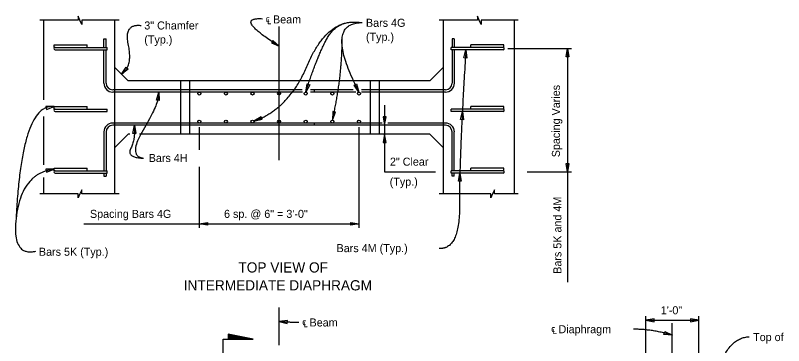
# Model space of a CAD drawing. Extents: x 120693.4 to 120747.1, y 120647.1 to 120670.1.
# Drawn here: x 120693.92 to 120708.35, y 120661.74 to 120667.95 of the extents above; entities that cross this region are included whole.
import ezdxf

# ---------------------------------------------------------------- set-up
doc = ezdxf.new("R2010")
doc.units = 0
for name, color, linetype in [('BeamConc', 7, 'Continuous'), ('CL_Major', 7, 'Continuous'), ('Dimension', 7, 'Continuous'), ('Miscellaneous', 7, 'Continuous'), ('Rebar', 7, 'Continuous'), ('TextStructures', 7, 'Continuous')]:
    doc.layers.add(name, color=color, linetype=linetype)

msp = doc.modelspace()

# ---------------------------------------------------------------- linework, layer by layer
at = {"layer": 'BeamConc'}
for p, q in [((120694.456, 120666.36), (120694.456, 120667.857)), ((120695.789, 120664.594), (120695.789, 120667.857)), ((120701.956, 120667.857), (120701.956, 120664.594)), ((120703.289, 120667.857), (120703.289, 120664.594)), ((120696.039, 120666.716), (120695.789, 120666.966)), ((120701.956, 120666.966), (120701.706, 120666.716)), ((120701.706, 120666.716), (120696.039, 120666.716)), ((120694.456, 120665.14), (120694.456, 120666.05)), ((120696.039, 120665.716), (120695.789, 120665.466)), ((120696.067, 120665.716), (120696.039, 120665.716)), ((120701.706, 120665.716), (120696.247, 120665.716)), ((120701.956, 120665.466), (120701.706, 120665.716)), ((120694.456, 120664.594), (120694.456, 120664.9))]:
    msp.add_line(p, q, dxfattribs=at)
at = {"layer": 'CL_Major'}
for p, q in [((120698.873, 120665.226), (120698.873, 120667.737)), ((120698.873, 120661.748), (120698.873, 120662.457)), ((120706.259, 120654.599), (120706.259, 120662.164))]:
    msp.add_line(p, q, dxfattribs=at)
at = {"layer": 'Dimension'}
for p, q in [((120703.171, 120667.326), (120704.365, 120667.326)), ((120704.289, 120667.326), (120704.289, 120662.934)), ((120700.855, 120666.263), (120700.855, 120665.01)), ((120697.373, 120665.848), (120697.373, 120665.419)), ((120700.373, 120665.848), (120700.373, 120663.954)), ((120697.373, 120665.1), (120697.373, 120663.954)), ((120700.855, 120665.01), (120701.812, 120665.01)), ((120703.534, 120665.009), (120704.365, 120665.009)), ((120695.206, 120664.029), (120700.373, 120664.029)), ((120705.759, 120660.46), (120705.759, 120662.293)), ((120706.759, 120660.46), (120706.759, 120662.293)), ((120705.759, 120662.218), (120706.759, 120662.218)), ((120698.383, 120661.861), (120697.914, 120661.944)), ((120697.914, 120661.934), (120698.383, 120661.861)), ((120698.383, 120661.861), (120697.914, 120661.921)), ((120697.914, 120661.907), (120698.383, 120661.861)), ((120698.383, 120661.861), (120697.914, 120661.894)), ((120697.914, 120661.879), (120698.383, 120661.861))]:
    msp.add_line(p, q, dxfattribs=at)
for points in [[(120695.865, 120667.857), (120695.166, 120667.857), (120695.166, 120667.779), (120695.132, 120667.857), (120695.098, 120667.934), (120695.098, 120667.857), (120694.38, 120667.857)], [(120703.365, 120667.857), (120702.666, 120667.857), (120702.666, 120667.779), (120702.632, 120667.857), (120702.598, 120667.934), (120702.598, 120667.857), (120701.88, 120667.857)], [(120695.865, 120664.594), (120695.166, 120664.594), (120695.166, 120664.671), (120695.132, 120664.594), (120695.098, 120664.516), (120695.098, 120664.594), (120694.38, 120664.594)], [(120703.365, 120664.594), (120702.918, 120664.594), (120702.918, 120664.671), (120702.884, 120664.594), (120702.85, 120664.516), (120702.85, 120664.594), (120701.88, 120664.594)], [(120697.82, 120661.486), (120697.82, 120661.861), (120698.383, 120661.861), (120697.914, 120661.955), (120697.914, 120661.861)]]:
    msp.add_lwpolyline(points, dxfattribs=at)
for points in [[(120698.873, 120667.368), (120698.755, 120667.474), (120698.727, 120667.429)], [(120704.289, 120667.326), (120704.316, 120667.17), (120704.263, 120667.17)], [(120702.382, 120667.302), (120702.398, 120667.145), (120702.345, 120667.148)], [(120695.914, 120666.841), (120696.002, 120666.973), (120696.04, 120666.937)], [(120699.372, 120666.507), (120699.4, 120666.663), (120699.45, 120666.645)], [(120700.372, 120666.507), (120700.28, 120666.635), (120700.327, 120666.659)], [(120696.614, 120666.507), (120696.62, 120666.349), (120696.567, 120666.356)], [(120694.65, 120666.234), (120694.492, 120666.233), (120694.501, 120666.181)], [(120698.4, 120665.961), (120698.555, 120665.995), (120698.535, 120666.044)], [(120699.873, 120665.981), (120699.934, 120666.127), (120699.883, 120666.139)], [(120700.855, 120665.882), (120700.882, 120666.039), (120700.829, 120666.039)], [(120702.316, 120666.143), (120702.335, 120665.986), (120702.282, 120665.989)], [(120696.154, 120665.883), (120696.18, 120665.727), (120696.127, 120665.727)], [(120700.855, 120665.716), (120700.829, 120665.559), (120700.882, 120665.559)], [(120704.289, 120665.009), (120704.263, 120665.165), (120704.316, 120665.165)], [(120694.65, 120665.057), (120694.492, 120665.056), (120694.501, 120665.004)], [(120702.269, 120664.985), (120702.294, 120664.829), (120702.241, 120664.829)], [(120697.373, 120664.029), (120697.528, 120664.056), (120697.528, 120664.003)], [(120700.373, 120664.029), (120700.217, 120664.003), (120700.217, 120664.056)], [(120698.873, 120662.196), (120699.027, 120662.16), (120699.031, 120662.213)], [(120705.759, 120662.218), (120705.916, 120662.191), (120705.916, 120662.244)], [(120706.759, 120662.218), (120706.603, 120662.244), (120706.603, 120662.191)], [(120706.26, 120661.935), (120706.102, 120661.953), (120706.117, 120662.004)]]:
    msp.add_lwpolyline(points, close=True, dxfattribs=at)
for points in [[(120695.914, 120666.841), (120696.128, 120666.992), (120695.954, 120667.794), (120696.279, 120667.759)], [(120698.873, 120667.368), (120698.006, 120667.916), (120698.559, 120667.886)], [(120698.4, 120665.961), (120699.061, 120666.196), (120699.729, 120667.786), (120700.224, 120667.82)], [(120699.373, 120666.507), (120699.578, 120667.15), (120699.969, 120667.882), (120700.433, 120667.812)], [(120700.373, 120666.507), (120699.704, 120667.812), (120700.433, 120667.812)], [(120699.873, 120665.981), (120700.058, 120666.764), (120700.058, 120667.531)], [(120702.381, 120667.302), (120702.255, 120665.261), (120702.269, 120663.536), (120701.877, 120663.568)], [(120696.614, 120666.507), (120696.632, 120666.32), (120696.02, 120665.295), (120696.326, 120665.265)], [(120694.65, 120666.234), (120694.037, 120666.311), (120693.933, 120664.15)], [(120696.154, 120665.882), (120696.173, 120665.625), (120695.999, 120665.27), (120696.326, 120665.265)], [(120694.65, 120665.057), (120694.052, 120664.991), (120693.828, 120663.407), (120694.302, 120663.517)], [(120698.873, 120662.195), (120699.059, 120662.184), (120699.246, 120662.18)], [(120706.259, 120661.936), (120705.893, 120662.05), (120705.527, 120662.05)], [(120707.024, 120660.718), (120707.154, 120661.882), (120707.703, 120661.908)]]:
    msp.add_open_spline(points, degree=2, dxfattribs=at)
at = {"layer": 'Miscellaneous'}
for p, q in [((120697.022, 120666.716), (120697.022, 120665.716)), ((120697.189, 120666.716), (120697.189, 120665.716)), ((120700.584, 120666.716), (120700.584, 120665.716)), ((120700.751, 120666.716), (120700.751, 120665.716))]:
    msp.add_line(p, q, dxfattribs=at)
at = {"layer": 'Rebar'}
for p, q in [((120695.581, 120667.507), (120695.623, 120667.507)), ((120695.581, 120667.344), (120695.581, 120667.507)), ((120695.623, 120667.344), (120695.623, 120667.507)), ((120702.164, 120667.507), (120702.123, 120667.507)), ((120702.123, 120667.507), (120702.123, 120667.344)), ((120702.164, 120667.507), (120702.164, 120667.344)), ((120694.65, 120667.344), (120694.65, 120667.396)), ((120694.65, 120667.396), (120695.27, 120667.396)), ((120694.65, 120667.344), (120695.643, 120667.344)), ((120695.27, 120667.344), (120695.27, 120667.396)), ((120695.643, 120667.302), (120695.643, 120667.344)), ((120703.095, 120667.344), (120702.102, 120667.344)), ((120702.102, 120667.302), (120702.102, 120667.344)), ((120703.095, 120667.396), (120702.475, 120667.396)), ((120702.475, 120667.344), (120702.475, 120667.396)), ((120703.095, 120667.344), (120703.095, 120667.396)), ((120694.664, 120667.302), (120695.643, 120667.302)), ((120695.581, 120666.674), (120695.581, 120667.302)), ((120695.623, 120666.674), (120695.623, 120667.302)), ((120703.081, 120667.302), (120702.102, 120667.302)), ((120702.123, 120667.302), (120702.123, 120666.674)), ((120702.164, 120667.302), (120702.164, 120666.674)), ((120699.31, 120666.507), (120695.747, 120666.507)), ((120699.306, 120666.549), (120695.748, 120666.549)), ((120700.264, 120666.549), (120699.46, 120666.549)), ((120700.314, 120666.507), (120699.46, 120666.507)), ((120699.539, 120666.507), (120699.539, 120666.549)), ((120701.998, 120666.549), (120700.423, 120666.549)), ((120701.998, 120666.507), (120700.423, 120666.507)), ((120694.65, 120666.185), (120694.65, 120666.237)), ((120694.65, 120666.237), (120695.27, 120666.237)), ((120694.65, 120666.185), (120695.643, 120666.185)), ((120695.27, 120666.185), (120695.27, 120666.237)), ((120695.643, 120666.143), (120695.643, 120666.185)), ((120703.095, 120666.185), (120702.102, 120666.185)), ((120702.102, 120666.143), (120702.102, 120666.185)), ((120703.095, 120666.237), (120702.475, 120666.237)), ((120702.475, 120666.185), (120702.475, 120666.237)), ((120703.095, 120666.185), (120703.095, 120666.237)), ((120694.664, 120666.143), (120695.643, 120666.143)), ((120703.081, 120666.143), (120702.102, 120666.143)), ((120700.806, 120665.924), (120695.747, 120665.924)), ((120701.998, 120665.882), (120695.748, 120665.882)), ((120699.539, 120665.882), (120699.539, 120665.924)), ((120701.998, 120665.924), (120700.914, 120665.924)), ((120695.581, 120665.758), (120695.581, 120665.027)), ((120695.623, 120665.757), (120695.623, 120665.027)), ((120702.123, 120665.027), (120702.123, 120665.757)), ((120702.164, 120665.027), (120702.164, 120665.758)), ((120694.65, 120665.027), (120694.65, 120665.079)), ((120694.65, 120665.079), (120695.27, 120665.079)), ((120694.65, 120665.027), (120695.643, 120665.027)), ((120695.27, 120665.027), (120695.27, 120665.079)), ((120695.643, 120664.985), (120695.643, 120665.027)), ((120703.095, 120665.027), (120702.102, 120665.027)), ((120702.102, 120664.985), (120702.102, 120665.027)), ((120703.095, 120665.079), (120702.475, 120665.079)), ((120702.475, 120665.027), (120702.475, 120665.079)), ((120703.095, 120665.027), (120703.095, 120665.079)), ((120694.664, 120664.985), (120695.643, 120664.985)), ((120695.581, 120664.985), (120695.581, 120664.924)), ((120695.581, 120664.924), (120695.623, 120664.924)), ((120695.623, 120664.985), (120695.623, 120664.924)), ((120703.081, 120664.985), (120702.102, 120664.985)), ((120702.123, 120664.924), (120702.123, 120664.985)), ((120702.164, 120664.924), (120702.123, 120664.924)), ((120702.164, 120664.924), (120702.164, 120664.985))]:
    msp.add_line(p, q, dxfattribs=at)
for centre in [(120697.373, 120666.479), (120697.873, 120666.479), (120698.373, 120666.479), (120698.873, 120666.479), (120699.373, 120666.479), (120699.873, 120666.479), (120700.373, 120666.479), (120697.373, 120665.953), (120697.873, 120665.953), (120698.373, 120665.953), (120698.873, 120665.953), (120699.373, 120665.953), (120699.873, 120665.953), (120700.373, 120665.953)]:
    msp.add_circle(centre, 0.0286, dxfattribs=at)
for centre, radius, start, end in [((120694.664, 120667.323), 0.0209, 81.4319, 269.9425), ((120703.081, 120667.323), 0.0209, 270.0575, 98.5681), ((120695.748, 120666.674), 0.167, 180, 270), ((120695.748, 120666.674), 0.125, 180, 270), ((120701.998, 120666.674), 0.125, 270, 360), ((120701.998, 120666.674), 0.167, 270, 360), ((120694.664, 120666.164), 0.0209, 81.4319, 269.9425), ((120703.081, 120666.164), 0.0209, 270.0575, 98.5681), ((120695.748, 120665.757), 0.167, 90, 180), ((120695.748, 120665.757), 0.125, 90, 180), ((120701.998, 120665.757), 0.167, 0, 90), ((120701.998, 120665.757), 0.125, 0, 90), ((120694.664, 120665.006), 0.0209, 81.4319, 269.9425), ((120703.081, 120665.006), 0.0209, 270.0575, 98.5681)]:
    msp.add_arc(centre, radius, start, end, dxfattribs=at)

# ---------------------------------------------------------------- texts
at = {"layer": 'Dimension'}
for s, height, p in [('3" Chamfer', 0.1512, (120696.34, 120667.683)), ('Bars 4G', 0.1512, (120700.504, 120667.733)), ('(Typ.)', 0.1512, (120700.504, 120667.469)), ('(Typ.)', 0.1512, (120696.34, 120667.419)), ('TOP VIEW OF', 0.192, (120698.108, 120663.115)), ('INTERMEDIATE DIAPHRAGM', 0.192, (120697.081, 120662.779)), ('Top of', 0.1512, (120707.777, 120661.826))]:
    msp.add_text(s, height=height, dxfattribs=at).set_placement(p)
at = {"layer": 'TextStructures'}
for s, p in [('℄ Beam', (120698.62, 120667.797)), ('Bars 4H', (120696.423, 120665.192)), ('2" Clear', (120700.954, 120665.123)), ('(Typ.)', (120700.95, 120664.746)), ('Spacing Bars 4G', (120695.319, 120664.142)), ('6 sp. @ 6" = 3\'-0"', (120697.838, 120664.142)), ('Bars 5K (Typ.)', (120694.36, 120663.43)), ('Bars 4M (Typ.)', (120699.952, 120663.498)), ('1\'-0"', (120706.042, 120662.33)), ('℄ Beam', (120699.306, 120662.101)), ('℄ Diaphragm', (120703.983, 120661.974))]:
    msp.add_text(s, height=0.1512, dxfattribs=at).set_placement(p)
for s, p in [('Spacing Varies', (120704.148, 120665.281)), ('Bars 5K and 4M', (120704.176, 120663.091))]:
    msp.add_text(s, height=0.1512, rotation=90, dxfattribs=at).set_placement(p)

doc.saveas('drawing.dxf')
